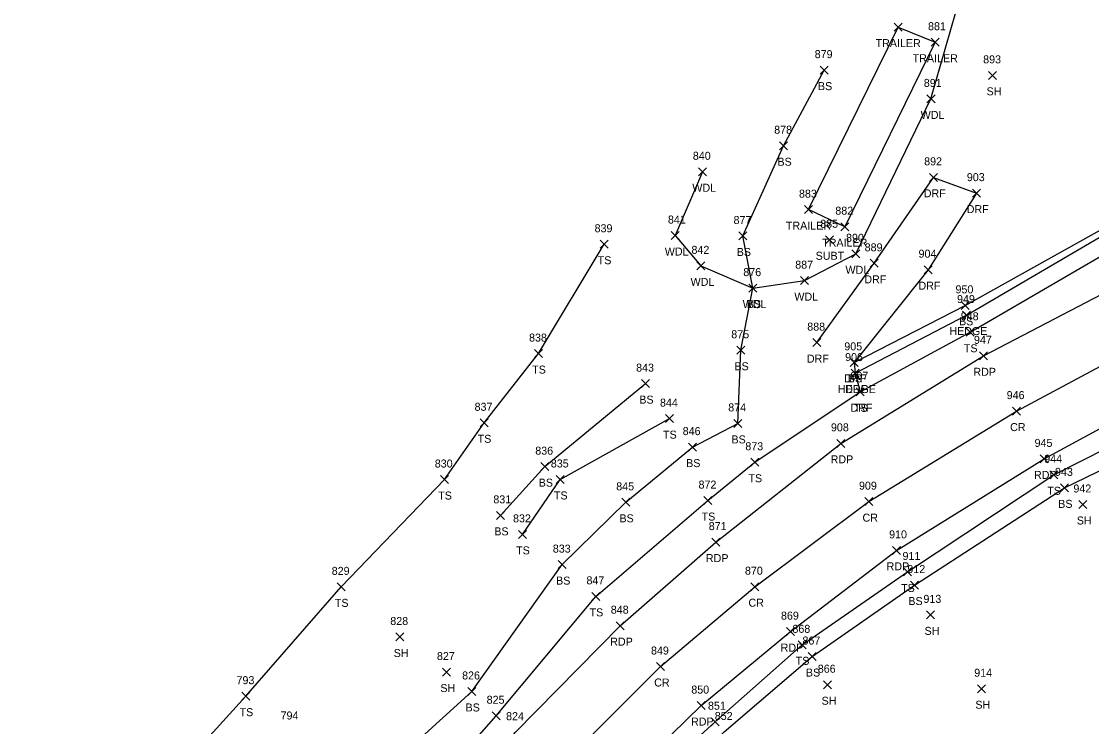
# Model space of a CAD drawing. Extents: x 1586965 to 1590952, y 716317 to 720029.
# Drawn here: x 1587140.2 to 1587407.7, y 719659.2 to 719835.6 of the extents above; entities that cross this region are included whole.
import ezdxf

# ---------------------------------------------------------------- set-up
doc = ezdxf.new("R2010")
doc.units = 0
for name, color, linetype in [('L_A', 7, 'Continuous'), ('L_I', 7, 'Continuous'), ('L_TIC', 7, 'Continuous'), ('LAHR', 7, 'Continuous'), ('LAWA', 7, 'Continuous'), ('LBC', 7, 'Continuous'), ('LELB', 7, 'Continuous'), ('P_A', 7, 'Continuous'), ('P_I', 7, 'Continuous'), ('P_TIC', 7, 'Continuous'), ('PET', 7, 'Continuous'), ('PRC', 7, 'Continuous'), ('R_A', 7, 'Continuous'), ('R_I', 7, 'Continuous'), ('R_TIC', 7, 'Continuous'), ('RDF', 7, 'Continuous'), ('U_A', 7, 'Continuous'), ('U_I', 7, 'Continuous'), ('U_TIC', 7, 'Continuous')]:
    doc.layers.add(name, color=color, linetype=linetype)

msp = doc.modelspace()

# ---------------------------------------------------------------- linework, layer by layer
at = {"layer": 'L_TIC'}
for points in [[(1587358.37, 719833.14), (1587360.37, 719835.14)], [(1587360.37, 719833.14), (1587358.37, 719835.14)], [(1587367.63, 719829.37), (1587369.63, 719831.37)], [(1587369.63, 719829.37), (1587367.63, 719831.37)], [(1587339.87, 719822.38), (1587341.87, 719824.38)], [(1587341.87, 719822.38), (1587339.87, 719824.38)], [(1587381.97, 719821.08), (1587383.97, 719823.08)], [(1587383.97, 719821.08), (1587381.97, 719823.08)], [(1587366.57, 719815.19), (1587368.57, 719817.19)], [(1587368.57, 719815.19), (1587366.57, 719817.19)], [(1587329.74, 719803.48), (1587331.74, 719805.48)], [(1587331.74, 719803.48), (1587329.74, 719805.48)], [(1587309.49, 719796.97), (1587311.49, 719798.97)], [(1587311.49, 719796.97), (1587309.49, 719798.97)], [(1587335.93, 719787.5), (1587337.93, 719789.5)], [(1587337.93, 719787.5), (1587335.93, 719789.5)], [(1587345.01, 719783.24), (1587347.01, 719785.24)], [(1587347.01, 719783.24), (1587345.01, 719785.24)], [(1587302.6, 719781.03), (1587304.6, 719783.03)], [(1587304.6, 719781.03), (1587302.6, 719783.03)], [(1587319.57, 719780.92), (1587321.57, 719782.92)], [(1587321.57, 719780.92), (1587319.57, 719782.92)], [(1587284.85, 719778.85), (1587286.85, 719780.85)], [(1587286.85, 719778.85), (1587284.85, 719780.85)], [(1587347.78, 719776.46), (1587349.78, 719778.46)], [(1587349.78, 719776.46), (1587347.78, 719778.46)], [(1587309.05, 719773.45), (1587311.05, 719775.45)], [(1587311.05, 719773.45), (1587309.05, 719775.45)], [(1587334.99, 719769.75), (1587336.99, 719771.75)], [(1587336.99, 719769.75), (1587334.99, 719771.75)], [(1587322.07, 719767.88), (1587324.07, 719769.88)], [(1587324.07, 719767.88), (1587322.07, 719769.88)], [(1587322.07, 719767.88), (1587324.07, 719769.88)], [(1587324.07, 719767.88), (1587322.07, 719769.88)], [(1587375.14, 719763.57), (1587377.14, 719765.57)], [(1587377.14, 719763.57), (1587375.14, 719765.57)], [(1587375.46, 719761.15), (1587377.46, 719763.15)], [(1587377.46, 719761.15), (1587375.46, 719763.15)], [(1587376.37, 719756.84), (1587378.37, 719758.84)], [(1587378.37, 719756.84), (1587376.37, 719758.84)], [(1587268.46, 719751.51), (1587270.46, 719753.51)], [(1587270.46, 719751.51), (1587268.46, 719753.51)], [(1587319, 719752.34), (1587321, 719754.34)], [(1587321, 719752.34), (1587319, 719754.34)], [(1587347.34, 719749.32), (1587349.34, 719751.32)], [(1587349.34, 719749.32), (1587347.34, 719751.32)], [(1587347.6, 719746.64), (1587349.6, 719748.64)], [(1587349.6, 719746.64), (1587347.6, 719748.64)], [(1587295.22, 719744), (1587297.22, 719746)], [(1587297.22, 719744), (1587295.22, 719746)], [(1587348.89, 719741.95), (1587350.89, 719743.95)], [(1587350.89, 719741.95), (1587348.89, 719743.95)], [(1587301.18, 719735.25), (1587303.18, 719737.25)], [(1587303.18, 719735.25), (1587301.18, 719737.25)], [(1587254.84, 719734.21), (1587256.84, 719736.21)], [(1587256.84, 719734.21), (1587254.84, 719736.21)], [(1587318.25, 719734.05), (1587320.25, 719736.05)], [(1587320.25, 719734.05), (1587318.25, 719736.05)], [(1587306.92, 719728.13), (1587308.92, 719730.13)], [(1587308.92, 719728.13), (1587306.92, 719730.13)], [(1587322.53, 719724.34), (1587324.53, 719726.34)], [(1587324.53, 719724.34), (1587322.53, 719726.34)], [(1587270.07, 719723.24), (1587272.07, 719725.24)], [(1587272.07, 719723.24), (1587270.07, 719725.24)], [(1587397.24, 719721.21), (1587399.24, 719723.21)], [(1587399.24, 719721.21), (1587397.24, 719723.21)], [(1587244.98, 719720.02), (1587246.98, 719722.02)], [(1587246.98, 719720.02), (1587244.98, 719722.02)], [(1587273.9, 719720.04), (1587275.9, 719722.04)], [(1587275.9, 719720.04), (1587273.9, 719722.04)], [(1587399.93, 719717.94), (1587401.93, 719719.94)], [(1587401.93, 719717.94), (1587399.93, 719719.94)], [(1587290.25, 719714.32), (1587292.25, 719716.32)], [(1587292.25, 719714.32), (1587290.25, 719716.32)], [(1587310.82, 719714.76), (1587312.82, 719716.76)], [(1587312.82, 719714.76), (1587310.82, 719716.76)], [(1587404.53, 719713.78), (1587406.53, 719715.78)], [(1587406.53, 719713.78), (1587404.53, 719715.78)], [(1587258.96, 719711.06), (1587260.96, 719713.06)], [(1587260.96, 719711.06), (1587258.96, 719713.06)], [(1587264.45, 719706.31), (1587266.45, 719708.31)], [(1587266.45, 719706.31), (1587264.45, 719708.31)], [(1587274.41, 719698.75), (1587276.41, 719700.75)], [(1587276.41, 719698.75), (1587274.41, 719700.75)], [(1587360.68, 719696.91), (1587362.68, 719698.91)], [(1587362.68, 719696.91), (1587360.68, 719698.91)], [(1587219.14, 719693.18), (1587221.14, 719695.18)], [(1587221.14, 719693.18), (1587219.14, 719695.18)], [(1587362.47, 719693.64), (1587364.47, 719695.64)], [(1587364.47, 719693.64), (1587362.47, 719695.64)], [(1587282.81, 719690.81), (1587284.81, 719692.81)], [(1587284.81, 719690.81), (1587282.81, 719692.81)], [(1587366.47, 719686.18), (1587368.47, 719688.18)], [(1587368.47, 719686.18), (1587366.47, 719688.18)], [(1587233.77, 719680.65), (1587235.77, 719682.65)], [(1587235.77, 719680.65), (1587233.77, 719682.65)], [(1587334.34, 719678.69), (1587336.34, 719680.69)], [(1587336.34, 719678.69), (1587334.34, 719680.69)], [(1587336.85, 719675.76), (1587338.85, 719677.76)], [(1587338.85, 719675.76), (1587336.85, 719677.76)], [(1587245.43, 719671.89), (1587247.43, 719673.89)], [(1587247.43, 719671.89), (1587245.43, 719673.89)], [(1587340.73, 719668.71), (1587342.73, 719670.71)], [(1587342.73, 719668.71), (1587340.73, 719670.71)], [(1587379.17, 719667.71), (1587381.17, 719669.71)], [(1587381.17, 719667.71), (1587379.17, 719669.71)], [(1587195.33, 719665.85), (1587197.33, 719667.85)], [(1587197.33, 719665.85), (1587195.33, 719667.85)], [(1587251.78, 719667.03), (1587253.78, 719669.03)], [(1587253.78, 719667.03), (1587251.78, 719669.03)], [(1587257.85, 719660.96), (1587259.85, 719662.96)], [(1587259.85, 719660.96), (1587257.85, 719662.96)], [(1587312.61, 719659.46), (1587314.61, 719661.46)], [(1587314.61, 719659.46), (1587312.61, 719661.46)]]:
    msp.add_lwpolyline(points, dxfattribs=at)
at = {"layer": 'LAHR'}
msp.add_lwpolyline([(1587348.6, 719747.64), (1587376.46, 719762.15), (1587411.99, 719782.97), (1587459.17, 719803.04), (1587473.56, 719809.91)], dxfattribs=at)
at = {"layer": 'LAWA'}
msp.add_lwpolyline([(1587310.49, 719797.97), (1587303.6, 719782.03), (1587310.05, 719774.45), (1587323.07, 719768.88), (1587335.99, 719770.75), (1587348.78, 719777.46), (1587367.57, 719816.19), (1587376.29, 719846.67), (1587402.77, 719859.66), (1587421.75, 719869.76), (1587448.54, 719840.99), (1587465.93, 719849.61), (1587481.33, 719848.44), (1587490.38, 719848.13), (1587509.69, 719854.18), (1587506.96, 719877.16), (1587490.41, 719892.21)], dxfattribs=at)
at = {"layer": 'LBC'}
for points in [[(1587359.37, 719834.14), (1587368.63, 719830.37), (1587346.01, 719784.24), (1587336.93, 719788.5)], [(1587336.93, 719788.5), (1587359.37, 719834.14)]]:
    msp.add_lwpolyline(points, dxfattribs=at)
at = {"layer": 'LELB'}
for points in [[(1587348.34, 719750.32), (1587376.14, 719764.57), (1587411.23, 719784.15), (1587458.35, 719804.18), (1587473.61, 719812.83), (1587489.06, 719812.38), (1587530.46, 719833.31), (1587544.39, 719838.73), (1587578.28, 719845.78), (1587610.35, 719855.43), (1587636.65, 719869.8), (1587651.78, 719871.98), (1587673.75, 719879.3), (1587684.98, 719885.25), (1587696.5, 719901.07), (1587712.21, 719917.3), (1587727.23, 719932.21), (1587743.8, 719944.38), (1587761.72, 719949.74)], [(1587348.34, 719750.32), (1587376.14, 719764.57), (1587411.23, 719784.15), (1587458.35, 719804.18), (1587473.61, 719812.83), (1587489.06, 719812.38), (1587530.46, 719833.31), (1587544.39, 719838.73), (1587578.28, 719845.78), (1587610.35, 719855.43), (1587636.65, 719869.8), (1587651.78, 719871.98), (1587673.75, 719879.3), (1587684.98, 719885.25), (1587696.5, 719901.07), (1587712.21, 719917.3), (1587727.23, 719932.21), (1587743.8, 719944.38), (1587761.72, 719949.74)], [(1586974.22, 719201.38), (1587004.64, 719224.97), (1587038.23, 719264.63), (1587070.35, 719308.83), (1587101.6, 719349.88), (1587119.36, 719390.75), (1587135.94, 719419.64), (1587149.18, 719457.32), (1587161.88, 719497.01), (1587171.82, 719537.32), (1587183.93, 719559.95), (1587196.31, 719595.67), (1587210.79, 719616.33), (1587226.54, 719644.19), (1587252.78, 719668.03), (1587275.41, 719699.75), (1587291.25, 719715.32), (1587307.92, 719729.13), (1587319.25, 719735.05), (1587320, 719753.34), (1587323.07, 719768.88), (1587320.57, 719781.92), (1587330.74, 719804.48), (1587340.87, 719823.38)], [(1586974.22, 719201.38), (1587004.64, 719224.97), (1587038.23, 719264.63), (1587070.35, 719308.83), (1587101.6, 719349.88), (1587119.36, 719390.75), (1587135.94, 719419.64), (1587149.18, 719457.32), (1587161.88, 719497.01), (1587171.82, 719537.32), (1587183.93, 719559.95), (1587196.31, 719595.67), (1587210.79, 719616.33), (1587226.54, 719644.19), (1587252.78, 719668.03), (1587275.41, 719699.75), (1587291.25, 719715.32), (1587307.92, 719729.13), (1587319.25, 719735.05), (1587320, 719753.34), (1587323.07, 719768.88), (1587320.57, 719781.92), (1587330.74, 719804.48), (1587340.87, 719823.38)], [(1587144.53, 719576.9), (1587159.2, 719612.92), (1587173.36, 719641.57), (1587196.33, 719666.85), (1587220.14, 719694.18), (1587245.98, 719721.02), (1587255.84, 719735.21), (1587269.46, 719752.51), (1587285.85, 719779.85)], [(1587144.53, 719576.9), (1587159.2, 719612.92), (1587173.36, 719641.57), (1587196.33, 719666.85), (1587220.14, 719694.18), (1587245.98, 719721.02), (1587255.84, 719735.21), (1587269.46, 719752.51), (1587285.85, 719779.85)], [(1586978.66, 719194.77), (1587009.14, 719220.21), (1587042.41, 719260.62), (1587074.55, 719306.69), (1587105.59, 719347.25), (1587126.81, 719387.29), (1587140.39, 719417.03), (1587155.04, 719455.09), (1587167.34, 719494.49), (1587179.82, 719533.81), (1587190.9, 719559.88), (1587204.29, 719592.61), (1587216.76, 719611.7), (1587236.63, 719636.62), (1587258.85, 719661.96), (1587283.81, 719691.81), (1587311.82, 719715.76), (1587323.53, 719725.34), (1587349.89, 719742.95), (1587377.37, 719757.84), (1587414.05, 719779.22)], [(1586978.66, 719194.77), (1587009.14, 719220.21), (1587042.41, 719260.62), (1587074.55, 719306.69), (1587105.59, 719347.25), (1587126.81, 719387.29), (1587140.39, 719417.03), (1587155.04, 719455.09), (1587167.34, 719494.49), (1587179.82, 719533.81), (1587190.9, 719559.88), (1587204.29, 719592.61), (1587216.76, 719611.7), (1587236.63, 719636.62), (1587258.85, 719661.96), (1587283.81, 719691.81), (1587311.82, 719715.76), (1587323.53, 719725.34), (1587349.89, 719742.95), (1587377.37, 719757.84), (1587414.05, 719779.22)], [(1587259.96, 719712.06), (1587271.07, 719724.24), (1587296.22, 719745)], [(1587259.96, 719712.06), (1587271.07, 719724.24), (1587296.22, 719745)], [(1587111.95, 719287.48), (1587133.61, 719303.61), (1587148.92, 719323.42), (1587167.88, 719366.46), (1587179.01, 719397.6), (1587173.15, 719399.12), (1587186.97, 719441.05), (1587200.36, 719482.43), (1587215.71, 719524.53), (1587222.82, 719545.46), (1587239.38, 719574.3), (1587247.92, 719589.42), (1587267.49, 719614.08), (1587286.95, 719636.16), (1587313.61, 719660.46), (1587335.34, 719679.69), (1587361.68, 719697.91), (1587398.24, 719722.21), (1587438.94, 719742.74)], [(1587111.95, 719287.48), (1587133.61, 719303.61), (1587148.92, 719323.42), (1587167.88, 719366.46), (1587179.01, 719397.6), (1587173.15, 719399.12), (1587186.97, 719441.05), (1587200.36, 719482.43), (1587215.71, 719524.53), (1587222.82, 719545.46), (1587239.38, 719574.3), (1587247.92, 719589.42), (1587267.49, 719614.08), (1587286.95, 719636.16), (1587313.61, 719660.46), (1587335.34, 719679.69), (1587361.68, 719697.91), (1587398.24, 719722.21), (1587438.94, 719742.74)], [(1587178.28, 719402.93), (1587189.21, 719440.25), (1587198.32, 719468.09), (1587203.86, 719481.06), (1587218.12, 719523.56), (1587224.35, 719543.95), (1587223.87, 719544.83), (1587224.18, 719545.53), (1587225.1, 719545.69), (1587240.99, 719573.37), (1587249.54, 719588.04), (1587270.51, 719611.5), (1587289.99, 719633.55), (1587315.89, 719657.91), (1587337.85, 719676.76), (1587363.47, 719694.64), (1587400.93, 719718.94), (1587441.36, 719738.52)], [(1587178.28, 719402.93), (1587189.21, 719440.25), (1587198.32, 719468.09), (1587203.86, 719481.06), (1587218.12, 719523.56), (1587224.35, 719543.95), (1587223.87, 719544.83), (1587224.18, 719545.53), (1587225.1, 719545.69), (1587240.99, 719573.37), (1587249.54, 719588.04), (1587270.51, 719611.5), (1587289.99, 719633.55), (1587315.89, 719657.91), (1587337.85, 719676.76), (1587363.47, 719694.64), (1587400.93, 719718.94), (1587441.36, 719738.52)], [(1587265.45, 719707.31), (1587274.9, 719721.04), (1587302.18, 719736.25)], [(1587265.45, 719707.31), (1587274.9, 719721.04), (1587302.18, 719736.25)]]:
    msp.add_lwpolyline(points, dxfattribs=at)
at = {"layer": 'P_TIC'}
for points in [[(1587379.68, 719750.95), (1587381.68, 719752.95)], [(1587381.68, 719750.95), (1587379.68, 719752.95)], [(1587387.91, 719737.13), (1587389.91, 719739.13)], [(1587389.91, 719737.13), (1587387.91, 719739.13)], [(1587344, 719729.07), (1587346, 719731.07)], [(1587346, 719729.07), (1587344, 719731.07)], [(1587394.82, 719725.18), (1587396.82, 719727.18)], [(1587396.82, 719725.18), (1587394.82, 719727.18)], [(1587351.02, 719714.49), (1587353.02, 719716.49)], [(1587353.02, 719714.49), (1587351.02, 719716.49)], [(1587312.81, 719704.37), (1587314.81, 719706.37)], [(1587314.81, 719704.37), (1587312.81, 719706.37)], [(1587357.98, 719702.31), (1587359.98, 719704.31)], [(1587359.98, 719702.31), (1587357.98, 719704.31)], [(1587322.51, 719693.22), (1587324.51, 719695.22)], [(1587324.51, 719693.22), (1587322.51, 719695.22)], [(1587288.89, 719683.48), (1587290.89, 719685.48)], [(1587290.89, 719683.48), (1587288.89, 719685.48)], [(1587331.49, 719681.99), (1587333.49, 719683.99)], [(1587333.49, 719681.99), (1587331.49, 719683.99)], [(1587298.95, 719673.27), (1587300.95, 719675.27)], [(1587300.95, 719673.27), (1587298.95, 719675.27)], [(1587309.1, 719663.5), (1587311.1, 719665.5)], [(1587311.1, 719663.5), (1587309.1, 719665.5)]]:
    msp.add_lwpolyline(points, dxfattribs=at)
at = {"layer": 'PET'}
for points in [[(1586981.32, 719191.44), (1587010.72, 719218.17), (1587046.97, 719256.26), (1587081.9, 719302.22), (1587109.59, 719344.47), (1587130.23, 719386.19), (1587143.83, 719415.56), (1587158.67, 719453.12), (1587172.27, 719492.43), (1587186.37, 719531.4), (1587196.72, 719557.08), (1587212.09, 719588.4), (1587223.39, 719607.14), (1587242.2, 719632.56), (1587263.71, 719657.85), (1587289.89, 719684.48), (1587313.81, 719705.37), (1587345, 719730.07), (1587380.68, 719751.95), (1587418.28, 719771.56)], [(1586998.3, 719170.55), (1587031.46, 719201.5), (1587048.24, 719215.72), (1587069.37, 719240.81), (1587083.56, 719258.07), (1587104.56, 719290.21), (1587133.86, 719331.71), (1587155.62, 719372.22), (1587169, 719404.76), (1587183.27, 719443.5), (1587197.56, 719483.83), (1587211.74, 719526.3), (1587221.19, 719546.28), (1587236.84, 719576.04), (1587246.13, 719590.54), (1587264.51, 719616.23), (1587283.97, 719638.96), (1587310.1, 719664.5), (1587332.49, 719682.99), (1587358.98, 719703.31), (1587395.82, 719726.18), (1587435.88, 719747.89)]]:
    msp.add_lwpolyline(points, dxfattribs=at)
at = {"layer": 'PRC'}
msp.add_lwpolyline([(1586989.8, 719181.42), (1587021.35, 719209.83), (1587057.54, 719247.82), (1587093.64, 719295.06), (1587121.6, 719338.75), (1587145.01, 719385.55), (1587156.05, 719410.32), (1587170.73, 719448.3), (1587185.3, 719487.87), (1587199.88, 719528.69), (1587209.21, 719551.28), (1587224.26, 719582.11), (1587235.22, 719599.27), (1587253.6, 719624.57), (1587274.17, 719648.49), (1587299.95, 719674.27), (1587323.51, 719694.22), (1587352.02, 719715.49), (1587388.91, 719738.13), (1587428.57, 719759.37)], dxfattribs=at)
msp.add_lwpolyline([(1586989.8, 719181.42), (1587021.35, 719209.83), (1587057.54, 719247.82), (1587093.64, 719295.06), (1587121.6, 719338.75), (1587145.01, 719385.55), (1587156.05, 719410.32), (1587170.73, 719448.3), (1587185.3, 719487.87), (1587199.88, 719528.69), (1587209.21, 719551.28), (1587224.26, 719582.11), (1587235.22, 719599.27), (1587253.6, 719624.57), (1587274.17, 719648.49), (1587299.95, 719674.27), (1587323.51, 719694.22), (1587352.02, 719715.49), (1587388.91, 719738.13), (1587428.57, 719759.37)], dxfattribs=at)
at = {"layer": 'R_TIC'}
for points in [[(1587367.22, 719795.58), (1587369.22, 719797.58)], [(1587369.22, 719795.58), (1587367.22, 719797.58)], [(1587377.97, 719791.63), (1587379.97, 719793.63)], [(1587379.97, 719791.63), (1587377.97, 719793.63)], [(1587352.36, 719774.08), (1587354.36, 719776.08)], [(1587354.36, 719774.08), (1587352.36, 719776.08)], [(1587365.9, 719772.49), (1587367.9, 719774.49)], [(1587367.9, 719772.49), (1587365.9, 719774.49)], [(1587338, 719754.25), (1587340, 719756.25)], [(1587340, 719754.25), (1587338, 719756.25)], [(1587347.34, 719749.32), (1587349.34, 719751.32)], [(1587349.34, 719749.32), (1587347.34, 719751.32)], [(1587347.6, 719746.64), (1587349.6, 719748.64)], [(1587349.6, 719746.64), (1587347.6, 719748.64)], [(1587348.89, 719741.95), (1587350.89, 719743.95)], [(1587350.89, 719741.95), (1587348.89, 719743.95)]]:
    msp.add_lwpolyline(points, dxfattribs=at)
at = {"layer": 'RDF'}
msp.add_lwpolyline([(1587339, 719755.25), (1587353.36, 719775.08), (1587368.22, 719796.58), (1587378.97, 719792.63), (1587366.9, 719773.49), (1587348.34, 719750.32), (1587348.6, 719747.64), (1587349.89, 719742.95)], dxfattribs=at)
at = {"layer": 'U_TIC'}
for points in [[(1587341.23, 719779.97), (1587343.23, 719781.97)], [(1587343.23, 719779.97), (1587341.23, 719781.97)]]:
    msp.add_lwpolyline(points, dxfattribs=at)

# ---------------------------------------------------------------- texts
at = {"layer": 'L_A'}
for s, p in [('TRAILER', (1587353.72, 719829.14)), ('TRAILER', (1587362.98, 719825.37)), ('BS', (1587339.31, 719818.38)), ('SH', (1587381.46, 719817.08)), ('WDL', (1587364.99, 719811.19)), ('BS', (1587329.18, 719799.48)), ('WDL', (1587307.91, 719792.97)), ('TRAILER', (1587331.29, 719783.5)), ('TRAILER', (1587340.37, 719779.24)), ('TS', (1587284.26, 719774.85)), ('WDL', (1587301.02, 719777.03)), ('BS', (1587319.01, 719776.92)), ('WDL', (1587346.19, 719772.46)), ('WDL', (1587307.47, 719769.45)), ('WDL', (1587333.41, 719765.75)), ('WDL', (1587320.49, 719763.88)), ('BS', (1587321.51, 719763.88)), ('BS', (1587374.58, 719759.57)), ('HEDGE', (1587372.16, 719757.15)), ('TS', (1587375.78, 719752.84)), ('BS', (1587318.44, 719748.34)), ('TS', (1587267.87, 719747.51)), ('BS', (1587346.78, 719745.32)), ('HEDGE', (1587344.3, 719742.64)), ('BS', (1587294.66, 719740)), ('TS', (1587348.3, 719737.95)), ('TS', (1587254.25, 719730.21)), ('TS', (1587300.59, 719731.25)), ('BS', (1587317.69, 719730.05)), ('BS', (1587306.36, 719724.13)), ('BS', (1587269.51, 719719.24)), ('TS', (1587321.94, 719720.34)), ('TS', (1587244.39, 719716.02)), ('TS', (1587273.31, 719716.04)), ('TS', (1587396.65, 719717.21)), ('BS', (1587399.37, 719713.94)), ('TS', (1587310.23, 719710.76)), ('BS', (1587289.69, 719710.32)), ('SH', (1587404.02, 719709.78)), ('BS', (1587258.41, 719707.06)), ('TS', (1587263.86, 719702.31)), ('BS', (1587273.85, 719694.75)), ('TS', (1587360.09, 719692.91)), ('TS', (1587218.55, 719689.18)), ('BS', (1587361.91, 719689.64)), ('TS', (1587282.22, 719686.81)), ('SH', (1587365.96, 719682.18)), ('SH', (1587233.26, 719676.65)), ('TS', (1587333.75, 719674.69)), ('BS', (1587336.29, 719671.76)), ('SH', (1587244.92, 719667.89)), ('BS', (1587251.22, 719663.03)), ('SH', (1587340.22, 719664.71)), ('SH', (1587378.66, 719663.71)), ('TS', (1587194.74, 719661.85))]:
    msp.add_text(s, height=2, dxfattribs=at).set_placement(p)
at = {"layer": 'L_I'}
for s, p in [('881', (1587366.83, 719833.37)), ('879', (1587338.5, 719826.38)), ('893', (1587380.61, 719825.08)), ('891', (1587365.77, 719819.19)), ('878', (1587328.37, 719807.48)), ('840', (1587308.04, 719800.97)), ('883', (1587334.57, 719791.5)), ('882', (1587343.65, 719787.24)), ('839', (1587283.48, 719782.85)), ('841', (1587301.81, 719785.03)), ('877', (1587318.21, 719784.92)), ('890', (1587346.33, 719780.46)), ('842', (1587307.69, 719777.45)), ('887', (1587333.63, 719773.75)), ('876', (1587320.65, 719771.88)), ('876', (1587320.65, 719771.88)), ('950', (1587373.69, 719767.57)), ('949', (1587374.08, 719765.15)), ('948', (1587375.01, 719760.84)), ('875', (1587317.64, 719756.34)), ('838', (1587267.09, 719755.51)), ('905', (1587345.9, 719753.32)), ('906', (1587346.1, 719750.64)), ('843', (1587293.86, 719748)), ('907', (1587347.45, 719745.95)), ('837', (1587253.48, 719738.21)), ('844', (1587299.82, 719739.25)), ('874', (1587316.89, 719738.05)), ('846', (1587305.5, 719732.13)), ('836', (1587268.65, 719727.24)), ('873', (1587321.16, 719728.34)), ('830', (1587243.53, 719724.02)), ('835', (1587272.54, 719724.04)), ('944', (1587395.88, 719725.21)), ('943', (1587398.57, 719721.94)), ('872', (1587309.46, 719718.76)), ('845', (1587288.89, 719718.32)), ('942', (1587403.17, 719717.78)), ('831', (1587258.17, 719715.06)), ('832', (1587263.09, 719710.31)), ('833', (1587273.04, 719702.75)), ('911', (1587360.45, 719700.91)), ('829', (1587217.77, 719697.18)), ('912', (1587361.67, 719697.64)), ('847', (1587281.45, 719694.81)), ('913', (1587365.68, 719690.18)), ('828', (1587232.41, 719684.65)), ('868', (1587332.93, 719682.69)), ('867', (1587335.44, 719679.76)), ('827', (1587244.07, 719675.89)), ('826', (1587250.36, 719671.03)), ('866', (1587339.27, 719672.71)), ('914', (1587378.38, 719671.71)), ('793', (1587193.97, 719669.85)), ('825', (1587256.49, 719664.96)), ('851', (1587311.82, 719663.46)), ('794', (1587204.99, 719661.02)), ('852', (1587313.52, 719660.91))]:
    msp.add_text(s, height=2, dxfattribs=at).set_placement(p)
at = {"layer": 'P_A'}
for s, p in [('RDP', (1587378.16, 719746.95)), ('CR', (1587387.34, 719733.13)), ('RDP', (1587342.48, 719725.07)), ('RDP', (1587393.31, 719721.18)), ('CR', (1587350.45, 719710.49)), ('RDP', (1587311.3, 719700.37)), ('RDP', (1587356.47, 719698.31)), ('CR', (1587321.94, 719689.22)), ('RDP', (1587287.38, 719679.48)), ('RDP', (1587329.98, 719677.99)), ('CR', (1587298.38, 719669.27)), ('RDP', (1587307.58, 719659.5))]:
    msp.add_text(s, height=2, dxfattribs=at).set_placement(p)
at = {"layer": 'P_I'}
for s, p in [('947', (1587378.31, 719754.95)), ('946', (1587386.49, 719741.13)), ('908', (1587342.56, 719733.07)), ('945', (1587393.46, 719729.18)), ('909', (1587349.57, 719718.49)), ('871', (1587312.01, 719708.37)), ('910', (1587357.1, 719706.31)), ('870', (1587321.06, 719697.22)), ('848', (1587287.53, 719687.48)), ('869', (1587330.07, 719685.99)), ('849', (1587297.58, 719677.27)), ('850', (1587307.65, 719667.5)), ('824', (1587261.35, 719660.85))]:
    msp.add_text(s, height=2, dxfattribs=at).set_placement(p)
at = {"layer": 'R_A'}
for p in [(1587365.76, 719791.58), (1587376.5, 719787.63), (1587350.9, 719770.08), (1587364.43, 719768.49), (1587336.54, 719750.25), (1587345.88, 719745.32), (1587346.13, 719742.64), (1587347.43, 719737.95)]:
    msp.add_text('DRF', height=2, dxfattribs=at).set_placement(p)
at = {"layer": 'R_I'}
for s, p in [('892', (1587365.86, 719799.58)), ('903', (1587376.53, 719795.63)), ('889', (1587350.99, 719778.08)), ('904', (1587364.46, 719776.49)), ('888', (1587336.64, 719758.25)), ('905', (1587345.9, 719753.32)), ('906', (1587346.1, 719750.64)), ('907', (1587347.45, 719745.95))]:
    msp.add_text(s, height=2, dxfattribs=at).set_placement(p)
at = {"layer": 'U_A'}
msp.add_text('SUBT', height=2, dxfattribs=at).set_placement((1587338.73, 719775.97))
at = {"layer": 'U_I'}
msp.add_text('885', height=2, dxfattribs=at).set_placement((1587339.87, 719783.97))

doc.saveas('drawing.dxf')
